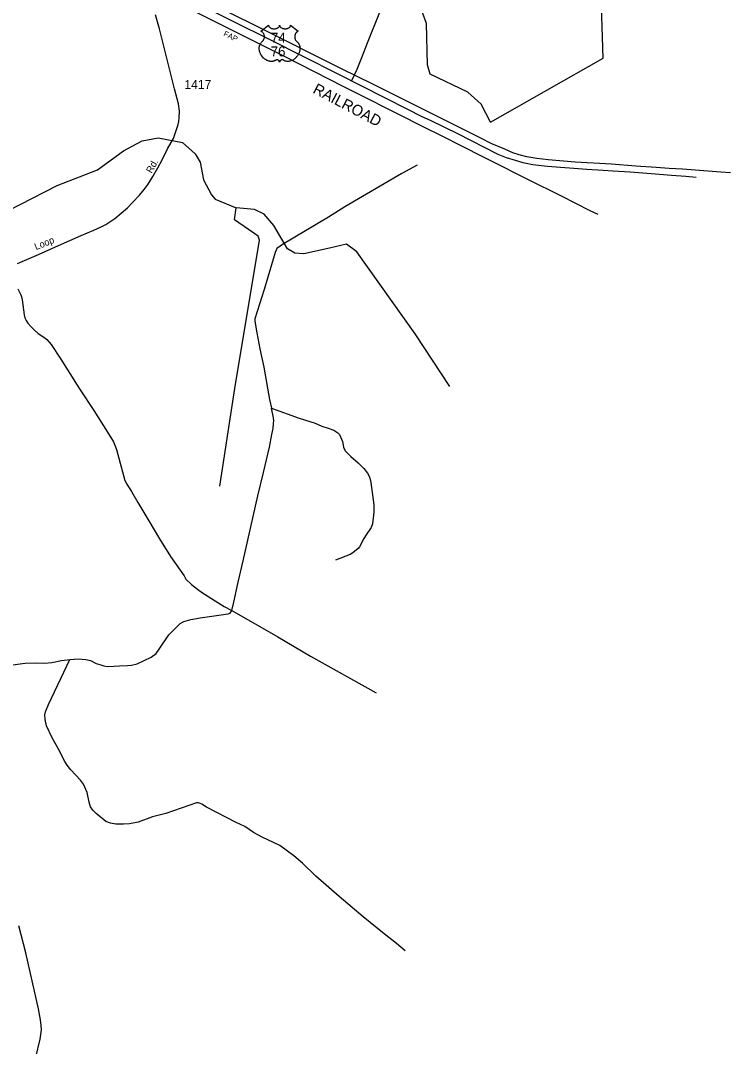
# Model space of a CAD drawing. Extents: x 2225501 to 2309677, y 165449 to 227696.
# Drawn here: x 2270573 to 2280362, y 174218 to 188364 of the extents above; entities that cross this region are included whole.
import ezdxf

# ---------------------------------------------------------------- set-up
doc = ezdxf.new("R2010")
doc.units = 0
for name, color, linetype in [('E_RDY_CMT_EOP', 7, 'Continuous'), ('MARK ENDS WORD SYMBOL CELL', 7, 'Continuous'), ('Old_Level_3', 7, 'Continuous'), ('Old_Level_33', 7, 'Continuous'), ('Old_Level_41', 7, 'Continuous'), ('Old_Level_46', 7, 'Continuous'), ('P_HYD_Ditch_Flow_Line', 7, 'Continuous'), ('P_HYD_Pipe_Flowable_Fill', 7, 'Continuous'), ('P_HYD_RipRap_Pad_876_02_18in_Outlet_With_Ditch-Top_CELL', 7, 'Continuous'), ('Prop Support', 7, 'Continuous'), ('Scratch_Level_2', 7, 'Continuous'), ('Typical Terminator CELL', 7, 'Continuous')]:
    doc.layers.add(name, color=color, linetype=linetype)

msp = doc.modelspace()

# ---------------------------------------------------------------- linework, layer by layer
at = {"layer": 'Old_Level_3'}
for p, q in [((2275178, 187620), (2275154, 187569)), ((2275154, 187569), (2275136, 187536))]:
    msp.add_line(p, q, dxfattribs=at)
for points in [[(2275700, 188902), (2275521, 188473), (2275352, 188050), (2275276, 187849), (2275210, 187691), (2275178, 187620)], [(2276043, 186368), (2275832, 186254), (2275044, 185793), (2274818, 185653), (2274187, 185278), (2274151, 185255), (2274108, 185219), (2274096, 185198), (2274085, 185166), (2273932, 184657), (2273803, 184253), (2273805, 184219), (2273832, 184057), (2273874, 183836), (2273926, 183583), (2273980, 183296), (2274008, 183139), (2274034, 183018)], [(2270535, 184666), (2270577, 184582), (2270587, 184555), (2270596, 184513), (2270623, 184305), (2270634, 184265), (2270649, 184230), (2270674, 184192), (2270714, 184143), (2270759, 184098), (2270818, 184049), (2270907, 183988), (2270936, 183965), (2270968, 183931), (2270997, 183895), (2271128, 183697), (2271353, 183336), (2271395, 183272), (2271584, 182988), (2271774, 182688), (2271853, 182555), (2271875, 182511), (2271897, 182450), (2272013, 182020), (2272038, 181973), (2272102, 181872), (2272189, 181717), (2272344, 181466), (2272489, 181219), (2272642, 180974), (2272829, 180708), (2272854, 180662), (2272931, 180590), (2273015, 180523), (2273082, 180474), (2273381, 180286), (2273488, 180228)], [(2273488, 180228), (2273516, 180345), (2273573, 180618), (2273645, 180912), (2273846, 181810), (2273924, 182131), (2274005, 182483), (2274039, 182654), (2274058, 182740), (2274060, 182808), (2274064, 182844), (2274059, 182886), (2274034, 183018)], [(2274034, 183018), (2274417, 182883), (2274636, 182811), (2274729, 182771), (2274816, 182743), (2274895, 182714), (2274949, 182677), (2274972, 182654), (2275014, 182558), (2275027, 182481), (2275050, 182429), (2275129, 182353), (2275227, 182267), (2275307, 182186), (2275356, 182121), (2275383, 182071), (2275403, 181996), (2275444, 181687), (2275446, 181587), (2275428, 181424), (2275407, 181374), (2275338, 181273), (2275307, 181222), (2275246, 181107), (2275228, 181082), (2275155, 181025), (2275116, 181002), (2274917, 180922)], [(2271253, 179553), (2271371, 179565), (2271473, 179555), (2271537, 179538), (2271618, 179500), (2271678, 179479), (2271723, 179464), (2271773, 179455), (2271865, 179463), (2271937, 179464), (2272047, 179470), (2272101, 179477), (2272182, 179493), (2272373, 179588), (2272443, 179638), (2272486, 179697), (2272618, 179895), (2272774, 180048), (2272825, 180079), (2272921, 180107), (2273052, 180130), (2273437, 180183), (2273463, 180192), (2273488, 180228)], [(2273488, 180228), (2274121, 179866), (2274573, 179601), (2275475, 179093)], [(2270462, 179479), (2270638, 179501), (2270784, 179506), (2270910, 179504), (2271005, 179514), (2271139, 179538), (2271253, 179553)], [(2275878, 175536), (2275756, 175639), (2275587, 175770), (2275299, 176004), (2274967, 176288), (2274646, 176568), (2274462, 176744), (2274340, 176848), (2274255, 176912), (2274149, 176988), (2273905, 177106), (2273784, 177169), (2273664, 177249), (2273545, 177307), (2273139, 177517), (2273072, 177560), (2273026, 177575), (2272998, 177576), (2272576, 177432), (2272391, 177382), (2272195, 177311), (2272077, 177288), (2271995, 177282), (2271887, 177281), (2271813, 177295), (2271750, 177322), (2271616, 177429), (2271569, 177476), (2271538, 177522), (2271519, 177585), (2271494, 177721), (2271442, 177836), (2271399, 177891), (2271266, 178031), (2271215, 178098), (2271182, 178149), (2271091, 178325), (2271010, 178474), (2270933, 178640), (2270913, 178728), (2270910, 178790), (2270915, 178830), (2270957, 178931), (2271253, 179553)]]:
    msp.add_lwpolyline(points, dxfattribs=at)
at = {"layer": 'Old_Level_33'}
for points in [[(2270530, 185015), (2270820, 185139), (2271098, 185264), (2271410, 185399), (2271585, 185472), (2271683, 185520), (2271747, 185551), (2271804, 185588), (2271875, 185636), (2271960, 185706), (2272046, 185783), (2272118, 185853), (2272212, 185954), (2272280, 186035), (2272331, 186106), (2272398, 186212), (2272464, 186334), (2272528, 186444), (2272601, 186595), (2272681, 186739), (2272721, 186850), (2272746, 186931), (2272755, 186970), (2272762, 187029), (2272764, 187112), (2272753, 187216), (2272698, 187423), (2272490, 188251), (2272432, 188444)], [(2270783, 174072), (2270842, 174320), (2270860, 174446), (2270858, 174508), (2270846, 174585), (2270820, 174737), (2270647, 175508), (2270551, 175883)]]:
    msp.add_lwpolyline(points, dxfattribs=at)
at = {"layer": 'Old_Level_41'}
msp.add_lwpolyline([(2272488, 188734), (2272520, 188719), (2272922, 188518), (2273282, 188336), (2273777, 188087), (2274197, 187876), (2274622, 187659), (2275028, 187454), (2275340, 187296), (2275646, 187143), (2275867, 187032), (2276038, 186946), (2276485, 186723), (2276552, 186689), (2277052, 186436), (2277565, 186176), (2278026, 185945), (2278424, 185743), (2278532, 185693)], dxfattribs=at)
at = {"layer": 'Old_Level_46'}
for points in [[(2280362, 186265), (2280231, 186273), (2279701, 186313), (2279516, 186324), (2279339, 186336), (2279057, 186354), (2278721, 186383), (2278222, 186413), (2277849, 186444), (2277690, 186462), (2277556, 186485), (2277450, 186513), (2277362, 186540), (2277250, 186589), (2277073, 186664), (2276912, 186748), (2276736, 186835), (2276186, 187108), (2275430, 187486), (2275000, 187700), (2273873, 188264), (2272571, 188913)], [(2272532, 188836), (2272972, 188618), (2274019, 188097), (2274464, 187872), (2274957, 187623), (2275911, 187143), (2276095, 187047), (2276229, 186984), (2276596, 186805), (2277156, 186523), (2277270, 186476), (2277395, 186438), (2277499, 186405), (2277635, 186381), (2277841, 186354), (2278381, 186315), (2278609, 186299), (2278740, 186290), (2278980, 186279), (2279269, 186254), (2279551, 186230), (2279747, 186216), (2279890, 186205)]]:
    msp.add_lwpolyline(points, dxfattribs=at)
at = {"layer": 'P_HYD_RipRap_Pad_876_02_18in_Outlet_With_Ditch-Top_CELL'}
msp.add_lwpolyline([(2273993, 188301), (2273993, 188296), (2273994, 188291), (2273995, 188289), (2273997, 188283), (2274001, 188277), (2274007, 188271), (2274013, 188266), (2274018, 188263), (2274025, 188259), (2274033, 188256), (2274042, 188253), (2274052, 188251), (2274062, 188250), (2274072, 188250), (2274083, 188251), (2274095, 188253), (2274101, 188255), (2274107, 188257), (2274112, 188259), (2274119, 188263), (2274124, 188266), (2274128, 188269), (2274134, 188274), (2274138, 188280), (2274140, 188283), (2274142, 188286), (2274144, 188292), (2274144, 188295), (2274145, 188301), (2274145, 188296), (2274146, 188293), (2274147, 188290), (2274148, 188287), (2274150, 188282), (2274153, 188279), (2274157, 188273), (2274160, 188270), (2274163, 188268), (2274170, 188263), (2274179, 188259), (2274183, 188257), (2274187, 188255), (2274192, 188254), (2274198, 188252), (2274204, 188252), (2274209, 188251), (2274215, 188250), (2274220, 188250), (2274225, 188250), (2274231, 188251), (2274236, 188251), (2274242, 188252), (2274247, 188253), (2274254, 188255), (2274259, 188257), (2274264, 188259), (2274271, 188263), (2274276, 188266), (2274280, 188269), (2274285, 188273), (2274289, 188278), (2274292, 188282), (2274294, 188286), (2274295, 188290), (2274296, 188294), (2274297, 188298), (2274297, 188301), (2274403, 188217), (2274401, 188216), (2274395, 188213), (2274390, 188210), (2274383, 188205), (2274380, 188202), (2274377, 188199), (2274374, 188196), (2274371, 188193), (2274368, 188189), (2274366, 188184), (2274363, 188180), (2274361, 188176), (2274358, 188167), (2274356, 188162), (2274355, 188157), (2274354, 188148), (2274353, 188143), (2274353, 188139), (2274354, 188134), (2274354, 188129), (2274355, 188125), (2274356, 188121), (2274357, 188116), (2274359, 188110), (2274361, 188104), (2274366, 188095), (2274372, 188085), (2274377, 188080), (2274381, 188075), (2274388, 188070), (2274391, 188067), (2274395, 188063), (2274402, 188055), (2274405, 188051), (2274407, 188047), (2274410, 188043), (2274412, 188039), (2274414, 188035), (2274418, 188025), (2274421, 188017), (2274422, 188012), (2274424, 188002), (2274425, 187996), (2274426, 187986), (2274426, 187974), (2274425, 187962), (2274423, 187949), (2274421, 187940), (2274418, 187931), (2274415, 187923), (2274410, 187911), (2274406, 187902), (2274401, 187892), (2274397, 187885), (2274392, 187879), (2274387, 187871), (2274380, 187863), (2274372, 187854), (2274366, 187848), (2274358, 187840), (2274353, 187836), (2274346, 187831), (2274336, 187824), (2274326, 187819), (2274318, 187815), (2274311, 187811), (2274301, 187808), (2274285, 187804), (2274280, 187802), (2274273, 187801), (2274267, 187801), (2274260, 187800), (2274252, 187800), (2274244, 187801), (2274236, 187802), (2274228, 187804), (2274220, 187806), (2274212, 187809), (2274204, 187813), (2274191, 187821), (2274187, 187823), (2274185, 187824), (2274180, 187824), (2274175, 187823), (2274170, 187821), (2274167, 187820), (2274163, 187817), (2274160, 187815), (2274157, 187811), (2274154, 187808), (2274152, 187806), (2274149, 187800), (2274147, 187798), (2274146, 187794), (2274145, 187789), (2274143, 187795), (2274141, 187800), (2274139, 187804), (2274137, 187807), (2274133, 187811), (2274129, 187814), (2274125, 187818), (2274121, 187820), (2274118, 187822), (2274115, 187823), (2274111, 187824), (2274108, 187824), (2274105, 187824), (2274102, 187823), (2274097, 187820), (2274092, 187817), (2274087, 187814), (2274081, 187811), (2274077, 187809), (2274072, 187807), (2274066, 187805), (2274059, 187803), (2274053, 187802), (2274047, 187801), (2274040, 187800), (2274035, 187800), (2274029, 187800), (2274023, 187800), (2274017, 187801), (2274009, 187802), (2274002, 187804), (2273995, 187806), (2273988, 187808), (2273980, 187811), (2273970, 187815), (2273964, 187818), (2273953, 187825), (2273941, 187833), (2273931, 187841), (2273924, 187847), (2273914, 187857), (2273908, 187864), (2273899, 187876), (2273893, 187885), (2273889, 187891), (2273883, 187901), (2273880, 187908), (2273876, 187917), (2273873, 187926), (2273871, 187934), (2273869, 187939), (2273867, 187948), (2273866, 187955), (2273865, 187964), (2273864, 187973), (2273864, 187982), (2273864, 187989), (2273865, 187997), (2273866, 188006), (2273868, 188014), (2273870, 188019), (2273872, 188026), (2273875, 188033), (2273878, 188040), (2273882, 188046), (2273886, 188052), (2273890, 188058), (2273895, 188064), (2273901, 188069), (2273906, 188073), (2273912, 188079), (2273916, 188083), (2273920, 188088), (2273923, 188093), (2273925, 188097), (2273928, 188103), (2273930, 188108), (2273933, 188115), (2273934, 188120), (2273935, 188126), (2273936, 188132), (2273936, 188140), (2273936, 188146), (2273935, 188154), (2273934, 188161), (2273932, 188167), (2273930, 188174), (2273927, 188179), (2273923, 188186), (2273919, 188192), (2273914, 188198), (2273909, 188202), (2273905, 188206), (2273900, 188209), (2273895, 188212), (2273890, 188215), (2273886, 188216)], close=True, dxfattribs=at)
at = {"layer": 'Prop Support'}
msp.add_line((2273319, 181943), (2273529, 183292), dxfattribs=at)
for points in [[(2277052, 186964), (2278609, 187846), (2278575, 188860), (2276366, 192521), (2276275, 192480), (2273485, 190602), (2273477, 190563)], [(2273529, 183292), (2273868, 185334), (2273851, 185393), (2273524, 185616), (2273548, 185783)]]:
    msp.add_lwpolyline(points, dxfattribs=at)
at = {"layer": 'Typical Terminator CELL'}
for points in [[(2277052, 186964), (2276924, 187213), (2276739, 187377), (2276221, 187623), (2276186, 187755), (2276172, 188323), (2276121, 188462), (2276128, 188639), (2276059, 188820), (2275889, 189185), (2275503, 189556), (2274383, 189962), (2274155, 190245), (2273987, 190392), (2273477, 190563)], [(2266151, 183995), (2266675, 184034), (2266875, 184079), (2267024, 184155), (2267139, 184303), (2267352, 184732), (2267442, 184806), (2267559, 184850), (2268375, 184893), (2269205, 185182), (2269703, 185388), (2271079, 186090), (2271635, 186305), (2271991, 186567), (2272248, 186703), (2272472, 186745), (2272806, 186683), (2272982, 186525), (2273050, 186409), (2273094, 186169), (2273204, 185960), (2273255, 185903), (2273548, 185783)], [(2276493, 183320), (2276013, 184046), (2275211, 185173), (2275068, 185281), (2274835, 185226), (2274478, 185148), (2274353, 185157), (2274253, 185215), (2274066, 185537), (2273931, 185693), (2273798, 185758), (2273548, 185783)]]:
    msp.add_lwpolyline(points, dxfattribs=at)

# ---------------------------------------------------------------- texts
at = {"layer": 'E_RDY_CMT_EOP'}
msp.add_text('1417', height=125, dxfattribs=at).set_placement((2272832, 187419))
at = {"layer": 'MARK ENDS WORD SYMBOL CELL'}
for s, rotation, p in [('Rd.', 60.941, (2272381, 186250)), ('Loop', 22.0111, (2270787, 185197))]:
    msp.add_text(s, height=95, rotation=rotation, dxfattribs=at).set_placement(p)
at = {"layer": 'P_HYD_Ditch_Flow_Line'}
for s, p in [('74', (2274024, 188057)), ('76', (2274022, 187869))]:
    msp.add_text(s, height=137.5, dxfattribs=at).set_placement(p)
at = {"layer": 'P_HYD_Pipe_Flowable_Fill'}
msp.add_text('RAILROAD', height=150, rotation=332.1769, dxfattribs=at).set_placement((2274592, 187373))
at = {"layer": 'Scratch_Level_2'}
msp.add_text('FAP', height=75, rotation=334.6005, dxfattribs=at).set_placement((2273364, 188156))

doc.saveas('drawing.dxf')
